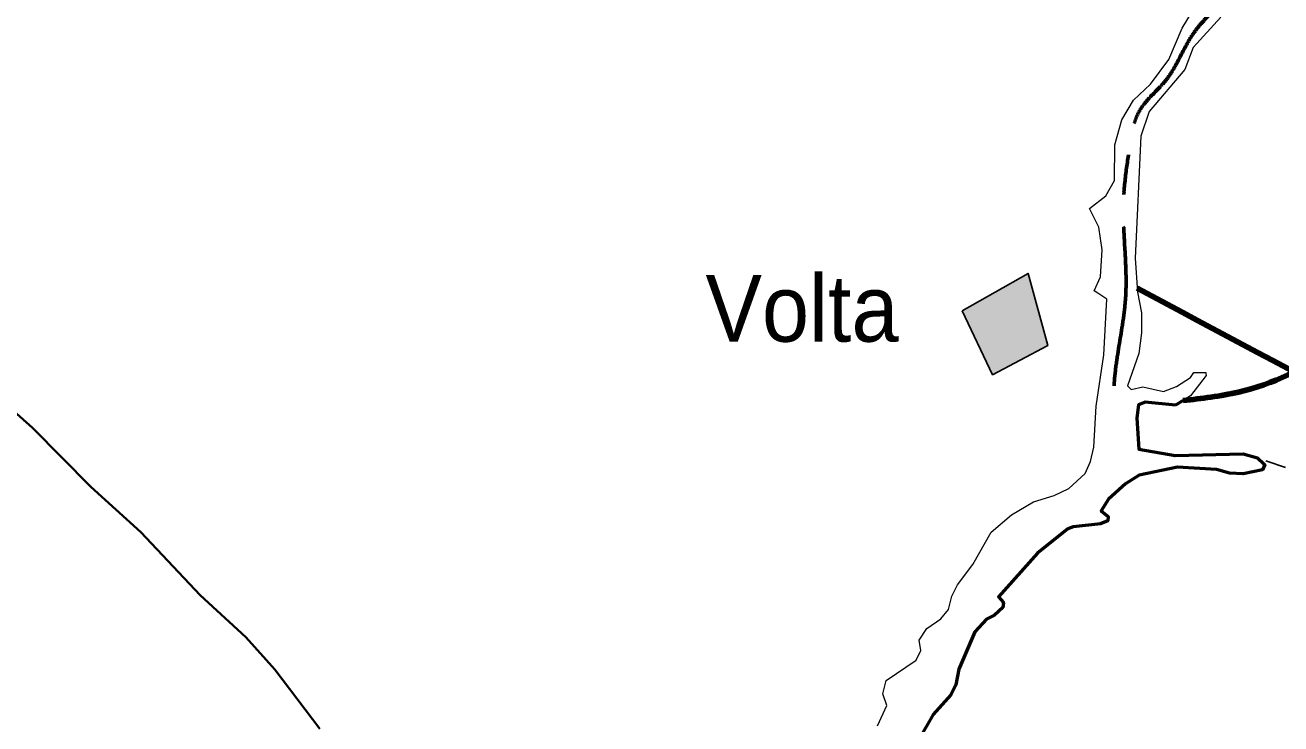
# Model space of a CAD drawing. Extents: x -1643653 to 4543381, y 1624270 to 13878484.
# Drawn here: x 584359 to 593776, y 8973933 to 8979171 of the extents above; entities that cross this region are included whole.
import ezdxf

# ---------------------------------------------------------------- set-up
doc = ezdxf.new("R2010")
doc.units = 0
doc.header["$LTSCALE"] = 200
doc.linetypes.add('LONG_DASH_SHORT_DASH', pattern=[9.9, 6, -1.2, 1.5, -1.2])
for name, color, linetype, lineweight in [('12', 7, 'Continuous', 25), ('21', 7, 'Continuous', 25), ('24', 7, 'Continuous', 25), ('25', 7, 'Continuous', 13), ('26', 7, 'Continuous', 106), ('28', 7, 'Continuous', 53), ('60', 7, 'Continuous', 13), ('7', 7, 'LONG_DASH_SHORT_DASH', 60), ('9', 7, 'Continuous', 90)]:
    doc.layers.add(name, color=color, linetype=linetype, lineweight=lineweight)
doc.layers.add('41', color=7, linetype='Continuous')

msp = doc.modelspace()

# ---------------------------------------------------------------- hatches: boundary and pattern name
at = {"layer": '21'}
msp.add_hatch(color=256, dxfattribs=at).paths.add_polyline_path([(591387.2, 8977029.8), (591614.3, 8976550.1), (592028.7, 8976768.6), (591880.1, 8977309.9)])

# ---------------------------------------------------------------- linework, layer by layer
at = {"layer": '12', "lineweight": 40}
msp.add_lwpolyline([(584108.1, 8976423.9), (584414.4, 8976152.1), (584852.4, 8975709.9), (585227.8, 8975368.9), (585671, 8974897.7), (586014.6, 8974582.2), (586230.8, 8974340.1), (586568.3, 8973894.4)], dxfattribs=at)
at = {"layer": '21'}
msp.add_lwpolyline([(591387.2, 8977029.8), (591614.3, 8976550.1), (592028.7, 8976768.6), (591880.1, 8977309.9)], close=True, dxfattribs=at)
at = {"layer": '24'}
msp.add_lwpolyline([(593663, 8975903.4), (593811, 8975854)], dxfattribs=at)
at = {"layer": '25'}
for points in [[(592340.2, 8977796.1), (592463.6, 8977889.9), (592529.4, 8978006.6), (592531.7, 8978272), (592582.8, 8978459.4), (592672, 8978608.1), (592799.5, 8978729.2), (592937.2, 8978913.6), (593037.2, 8979147.4), (593113.6, 8979274.7), (593249.5, 8979396.5)], [(592340.2, 8977796.1), (592463.6, 8977889.9), (592529.4, 8978006.6), (592531.7, 8978272), (592582.8, 8978459.4), (592672, 8978608.1), (592799.5, 8978729.2), (592937.2, 8978913.6), (593037.2, 8979147.4), (593113.6, 8979274.7), (593249.5, 8979396.5)], [(593326.1, 8979230.3), (593118.1, 8979003.2), (593056.2, 8978837.1), (592788.7, 8978522.9), (592727, 8978339.3), (592684.6, 8977422.8), (592701.6, 8977167.9), (592731.3, 8977014.7), (592731.4, 8976862.7), (592710.1, 8976709.1), (592625.3, 8976466.7), (592653, 8976439.2), (592742.2, 8976458.1), (592894.9, 8976424.2), (592992.8, 8976460.4), (593098.8, 8976528.3), (593123.6, 8976567.4), (593214.3, 8976567.6), (593214.6, 8976559.7)], [(593326.1, 8979230.3), (593118.1, 8979003.2), (593056.2, 8978837.1), (592788.7, 8978522.9), (592727, 8978339.3), (592684.6, 8977422.8), (592701.6, 8977167.9), (592731.3, 8977014.7), (592731.4, 8976862.7), (592710.1, 8976709.1), (592625.3, 8976466.7), (592653, 8976439.2), (592742.2, 8976458.1), (592894.9, 8976424.2), (592992.8, 8976460.4), (593098.8, 8976528.3), (593123.6, 8976567.4), (593214.3, 8976567.6), (593214.6, 8976559.7)], [(592403.5, 8977160.8), (592376.8, 8977178.1), (592423.3, 8977282.6), (592436.1, 8977486), (592410.8, 8977655.4), (592340.2, 8977796.1)], [(592403.5, 8977160.8), (592376.8, 8977178.1), (592423.3, 8977282.6), (592436.1, 8977486), (592410.8, 8977655.4), (592340.2, 8977796.1)], [(590751.6, 8973917.8), (590821.5, 8974070.5), (590792, 8974157.8), (590815.2, 8974257.2), (591040.4, 8974410.4), (591076.5, 8974482.4), (591063.8, 8974558.8), (591121.2, 8974648.3), (591227.2, 8974720.4), (591282.6, 8974788.8), (591308.2, 8974890.7), (591350.1, 8974974.6), (591465.3, 8975128.4), (591603.2, 8975370.3), (591756.1, 8975500), (591922, 8975597.8), (592075.7, 8975644.8), (592185.6, 8975697.8), (592308.6, 8975810.4), (592349.1, 8975899.9), (592374.4, 8976007.6), (592391.5, 8976313.7), (592449, 8976697.9), (592471.9, 8977116.8), (592403.5, 8977160.8)], [(590751.6, 8973917.8), (590821.5, 8974070.5), (590792, 8974157.8), (590815.2, 8974257.2), (591040.4, 8974410.4), (591076.5, 8974482.4), (591063.8, 8974558.8), (591121.2, 8974648.3), (591227.2, 8974720.4), (591282.6, 8974788.8), (591308.2, 8974890.7), (591350.1, 8974974.6), (591465.3, 8975128.4), (591603.2, 8975370.3), (591756.1, 8975500), (591922, 8975597.8), (592075.7, 8975644.8), (592185.6, 8975697.8), (592308.6, 8975810.4), (592349.1, 8975899.9), (592374.4, 8976007.6), (592391.5, 8976313.7), (592449, 8976697.9), (592471.9, 8977116.8), (592403.5, 8977160.8)], [(593214.6, 8976559.7), (593215.2, 8976544.7), (593099, 8976390.4), (592986.9, 8976322.5), (592758.7, 8976343.4), (592708.2, 8976324.4), (592695.2, 8976224.5), (592709.9, 8975991.5), (592983.9, 8975944.1), (593493.9, 8975956.8), (593602.1, 8975927.4), (593649.1, 8975881.7)], [(593214.6, 8976559.7), (593215.2, 8976544.7), (593099, 8976390.4), (592986.9, 8976322.5), (592758.7, 8976343.4), (592708.2, 8976324.4), (592695.2, 8976224.5), (592709.9, 8975991.5), (592983.9, 8975944.1), (593493.9, 8975956.8), (593602.1, 8975927.4), (593649.1, 8975881.7)], [(593649.1, 8975881.7), (593655, 8975876), (593638.1, 8975835.7), (593493.9, 8975806), (593392, 8975812.4), (593294, 8975840), (593001.4, 8975857), (592713.8, 8975797.2), (592610.3, 8975731.6), (592482.8, 8975616.5), (592429.9, 8975529.9), (592480.5, 8975487.5), (592478.3, 8975455.5), (592423.1, 8975432.1), (592219.4, 8975410.8), (592178.8, 8975393.7), (591951.5, 8975211), (591658.9, 8974884.4), (591696.9, 8974843.5), (591690.4, 8974805.5), (591629, 8974746.2), (591569.4, 8974716.2), (591482.2, 8974622.5), (591361.3, 8974342.6), (591339.9, 8974225.6), (591302.4, 8974150.2), (591167.7, 8974002.3), (591061.7, 8973815.6)], [(593649.1, 8975881.7), (593655, 8975876), (593638.1, 8975835.7), (593493.9, 8975806), (593392, 8975812.4), (593294, 8975840), (593001.4, 8975857), (592713.8, 8975797.2), (592610.3, 8975731.6), (592482.8, 8975616.5), (592429.9, 8975529.9), (592480.5, 8975487.5), (592478.3, 8975455.5), (592423.1, 8975432.1), (592219.4, 8975410.8), (592178.8, 8975393.7), (591951.5, 8975211), (591658.9, 8974884.4), (591696.9, 8974843.5), (591690.4, 8974805.5), (591629, 8974746.2), (591569.4, 8974716.2), (591482.2, 8974622.5), (591361.3, 8974342.6), (591339.9, 8974225.6), (591302.4, 8974150.2), (591167.7, 8974002.3), (591061.7, 8973815.6)]]:
    msp.add_lwpolyline(points, dxfattribs=at)
at = {"layer": '26'}
msp.add_spline([(593042.9, 8976356.4), (593459.4, 8976419.7), (594161.8, 8976760.1), (594545.8, 8977114.6), (594814.3, 8977291.5), (596052.8, 8977846), (596780.5, 8978160.9), (597647.4, 8978322.7), (598691.5, 8978280.2), (599825, 8978301), (600207.2, 8978324.8), (600219.9, 8978324.8), (601225.9, 8978295.2), (602040.5, 8978228.3), (602729, 8978352.6), (603275.7, 8978615.7), (603826.1, 8978691.5), (605382.2, 8979104.7), (606925.6, 8979530.7), (607614.7, 8979782.2), (608494.2, 8979905.8), (609628.7, 8980104.6), (610966.5, 8980200.8), (612239.3, 8980081.1), (613131.4, 8980179.2), (614149.6, 8980073.3), (614581.8, 8979931.6), (616361, 8979275.7), (617566.6, 8978533.2), (618237.8, 8977881.9), (618833.2, 8977319.9), (619759.6, 8976743.8), (620623, 8976295.2), (621512.5, 8975960.9), (621945, 8975870.1), (622544.2, 8975982.1), (622735.8, 8976070.3), (623374, 8976322), (623974.5, 8976675.6), (624627.1, 8977219.8), (625050.7, 8977803), (625410.5, 8978361.1), (625972.2, 8978587.6), (626239.9, 8978637.4), (628239.2, 8978616.5), (629272.1, 8978853.8), (630051.8, 8979346.6), (630703.5, 8979738.1), (631164.1, 8980105), (631534.8, 8980357.8), (632185.7, 8980596.8), (632989, 8980758.8), (633690, 8980870.4), (634328.2, 8981109.3), (634980.1, 8981526.3), (636460.7, 8982117.9), (637495.4, 8982660.5), (638159.4, 8982975.7), (638593.8, 8983228.2), (639449.6, 8983669.8), (641371.6, 8983483.9), (642032.9, 8983315.8), (642528.8, 8983186.6), (643277.3, 8982687.6), (644168, 8982544), (644675.9, 8982274.9), (645321.7, 8981636.4), (645853, 8981011.1), (646805.1, 8980473.1), (647606.1, 8980240.8), (648482.7, 8979868.5), (649626.6, 8979469.5), (650871.6, 8978943), (651404, 8978495.7), (652521.8, 8977995.2), (653308.2, 8977445.1), (653712.6, 8976883.9), (654308.9, 8976487.2), (655070.4, 8976039), (655983.7, 8975399.4)], degree=3, dxfattribs=at)
at = {"layer": '28'}
msp.add_line((593042.9, 8976356.4), (592986.9, 8976322.5), dxfattribs=at)
for points in [[(592986.9, 8976322.5), (592758.7, 8976343.4), (592708.2, 8976324.4), (592695.2, 8976224.5), (592709.9, 8975991.5), (592983.9, 8975944.1), (593493.9, 8975956.8), (593602.1, 8975927.4), (593649.1, 8975881.7)], [(593649.1, 8975881.7), (593655, 8975876), (593638.1, 8975835.7), (593493.9, 8975806), (593392, 8975812.4), (593294, 8975840), (593001.4, 8975857), (592713.8, 8975797.2), (592610.3, 8975731.6), (592482.8, 8975616.5), (592429.9, 8975529.9), (592480.5, 8975487.5), (592478.3, 8975455.5), (592423.1, 8975432.1), (592219.4, 8975410.8), (592178.8, 8975393.7), (591951.5, 8975211), (591658.9, 8974884.4), (591696.9, 8974843.5), (591690.4, 8974805.5), (591629, 8974746.2), (591569.4, 8974716.2), (591482.2, 8974622.5), (591361.3, 8974342.6), (591339.9, 8974225.6), (591302.4, 8974150.2), (591167.7, 8974002.3), (591061.7, 8973815.6)]]:
    msp.add_lwpolyline(points, dxfattribs=at)
msp.add_spline([(601221.6, 8978295.4), (600219.9, 8978324.8), (600207.2, 8978324.8), (599825, 8978301), (598691.5, 8978280.2), (597647.4, 8978322.7), (596780.5, 8978160.9), (596052.8, 8977846), (594814.3, 8977291.5), (594545.8, 8977114.6), (594161.8, 8976760.1), (593459.4, 8976419.7), (593042.9, 8976356.4)], degree=3, dxfattribs=at)
at = {"layer": '60', "lineweight": 25}
msp.add_spline([(814781, 9009175.5), (814787.2, 9009173.4), (814796.9, 9009173.4), (814799.4, 9009172.4), (814805.1, 9009174.5), (814805.6, 9009176.5), (814811.7, 9009179.5), (814811.7, 9009179.5), (814801.5, 9009181), (814790.7, 9009181.5), (814784.1, 9009183.1), (814777.4, 9009185.1), (814778.4, 9009175.5)], degree=3, dxfattribs=at)
at = {"layer": '7'}
msp.add_spline([(592525.2, 8976466.9), (592528.1, 8976506.5), (592612.5, 8977139.6), (592595.6, 8977840.2), (592646.2, 8978279.2), (592713.7, 8978524), (592916.2, 8978760.3), (593118.7, 8979106.4), (593264.9, 8979274.8)], degree=3, dxfattribs=at)
at = {"layer": '9'}
msp.add_spline([(592698.5, 8977198.4), (599903.5, 8973292.7), (608459.2, 8968138.2), (612674.8, 8965332.6), (616842, 8962096.4), (620005, 8958671.2), (621134, 8957974.7), (621473.4, 8956805.3), (621586.2, 8956597.5)], degree=3, dxfattribs=at)

# ---------------------------------------------------------------- texts
at = {"layer": '41', "width": 0.95}
msp.add_text('Volta', height=500, dxfattribs=at).set_placement((589461.3, 8976797.6))

doc.saveas('drawing.dxf')
